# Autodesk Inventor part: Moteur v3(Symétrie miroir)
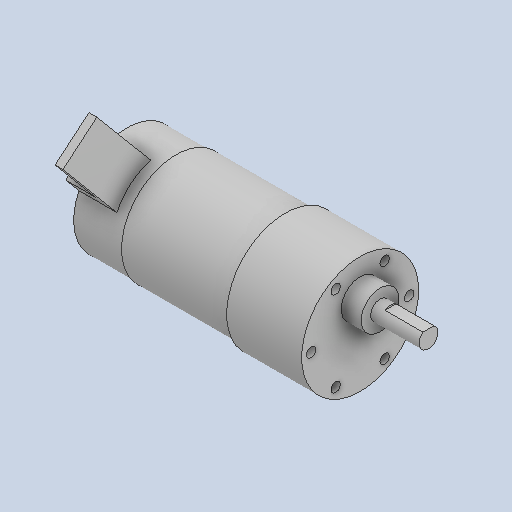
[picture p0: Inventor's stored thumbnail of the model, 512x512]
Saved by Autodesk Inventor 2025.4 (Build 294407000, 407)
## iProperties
Created: 2026-06
Part Number: Moteur v3(Symétrie miroir)
Material: Generic
Document SubType Name: Modeling
Designer: AdminForWorker
Density: 1 g/cm^3
Appearance: Default
Title: Moteur v3(Symétrie miroir)
Author: AdminForWorker
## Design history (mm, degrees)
feature "Body1"
body "Solid1"
